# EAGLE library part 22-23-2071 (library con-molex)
.100" (2.54mm) Center Header - 7 Pin
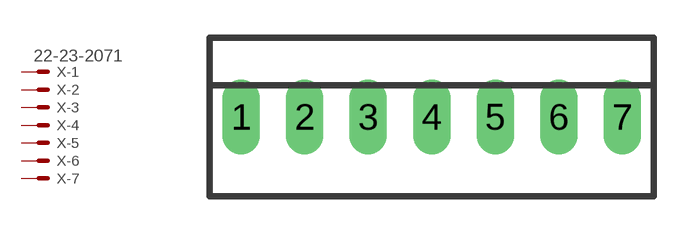
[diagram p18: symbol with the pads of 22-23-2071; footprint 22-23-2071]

Designator prefix X; gates -1=MV -2=M -3=M -4=M -5=M -6=M -7=M

## 22-23-2071 (MF: MOLEX; MPN: 22-23-2071; OC_FARNELL: 1654534; OC_NEWARK: 56H0445)  [22-23-2071]
1  -1:S  pas
2  -2:S  pas
3  -3:S  pas
4  -4:S  pas
5  -5:S  pas
6  -6:S  pas
7  -7:S  pas

## Footprint 22-23-2071 (pad centres in mm)
.100" (2.54mm) Center Header - 7 Pin
drill 1 long: 1 -7.62,0; 2 -5.08,0; 3 -2.54,0; 4 0,0; 5 2.54,0; 6 5.08,0; 7 7.62,0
